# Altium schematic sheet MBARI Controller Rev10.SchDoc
size C
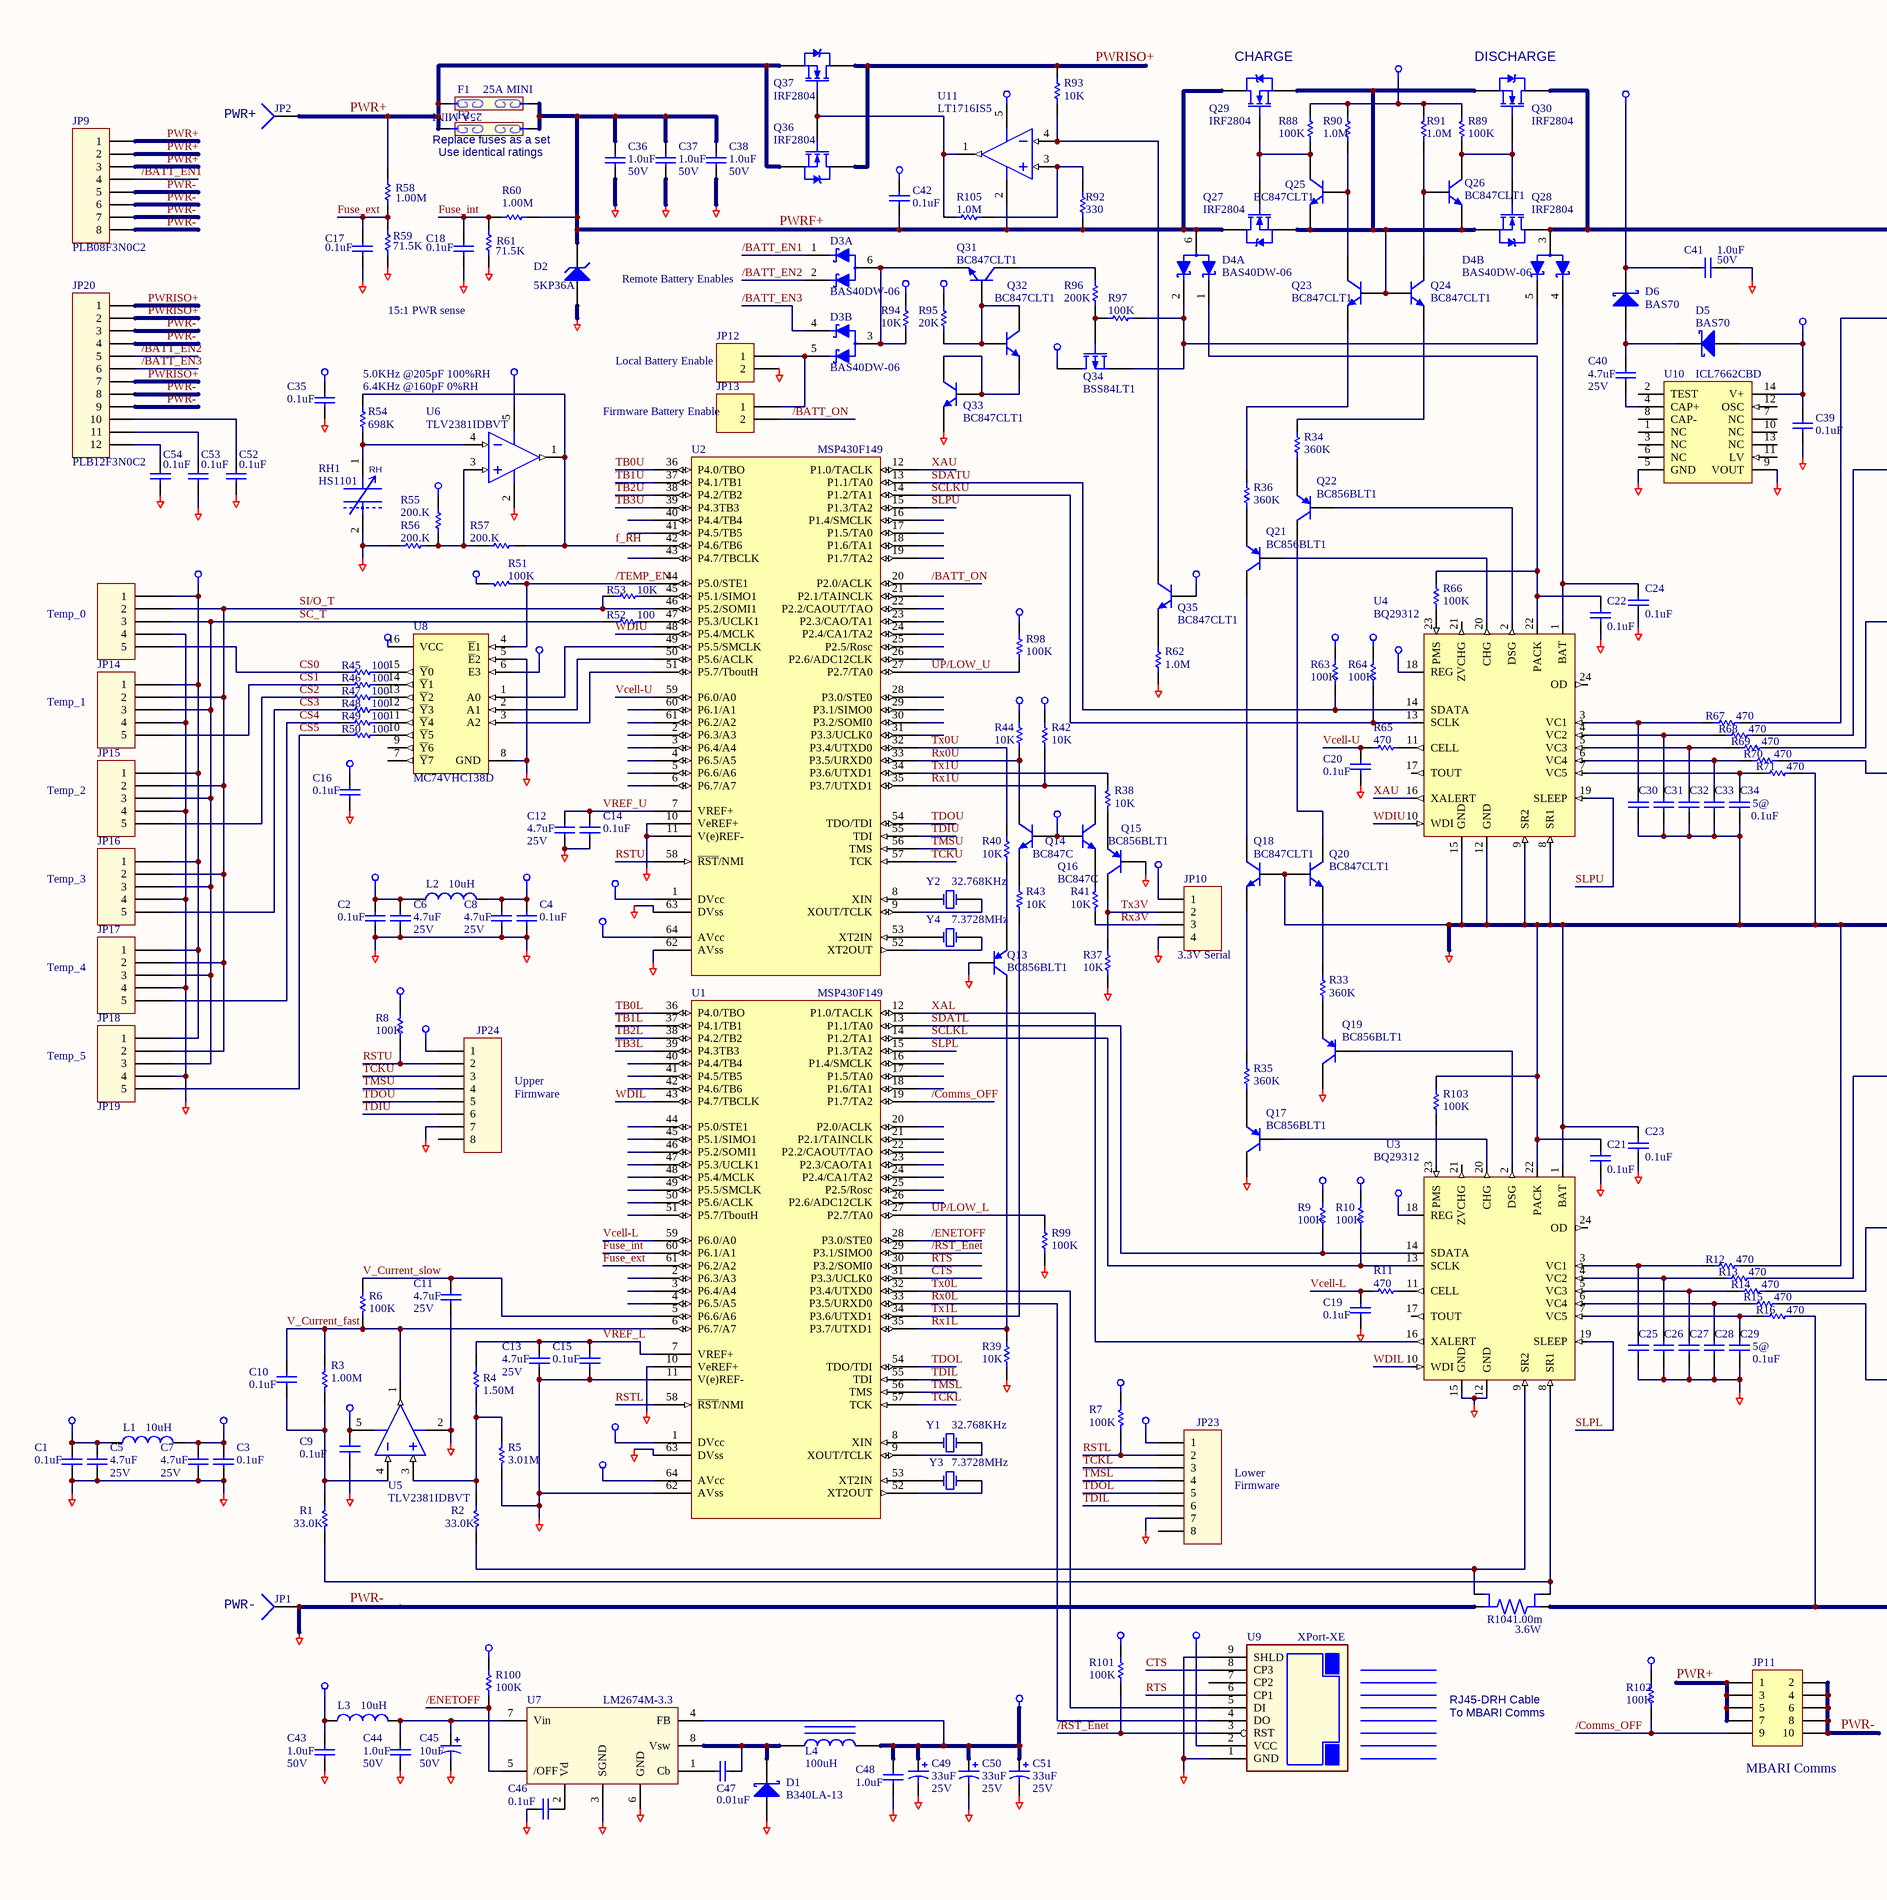
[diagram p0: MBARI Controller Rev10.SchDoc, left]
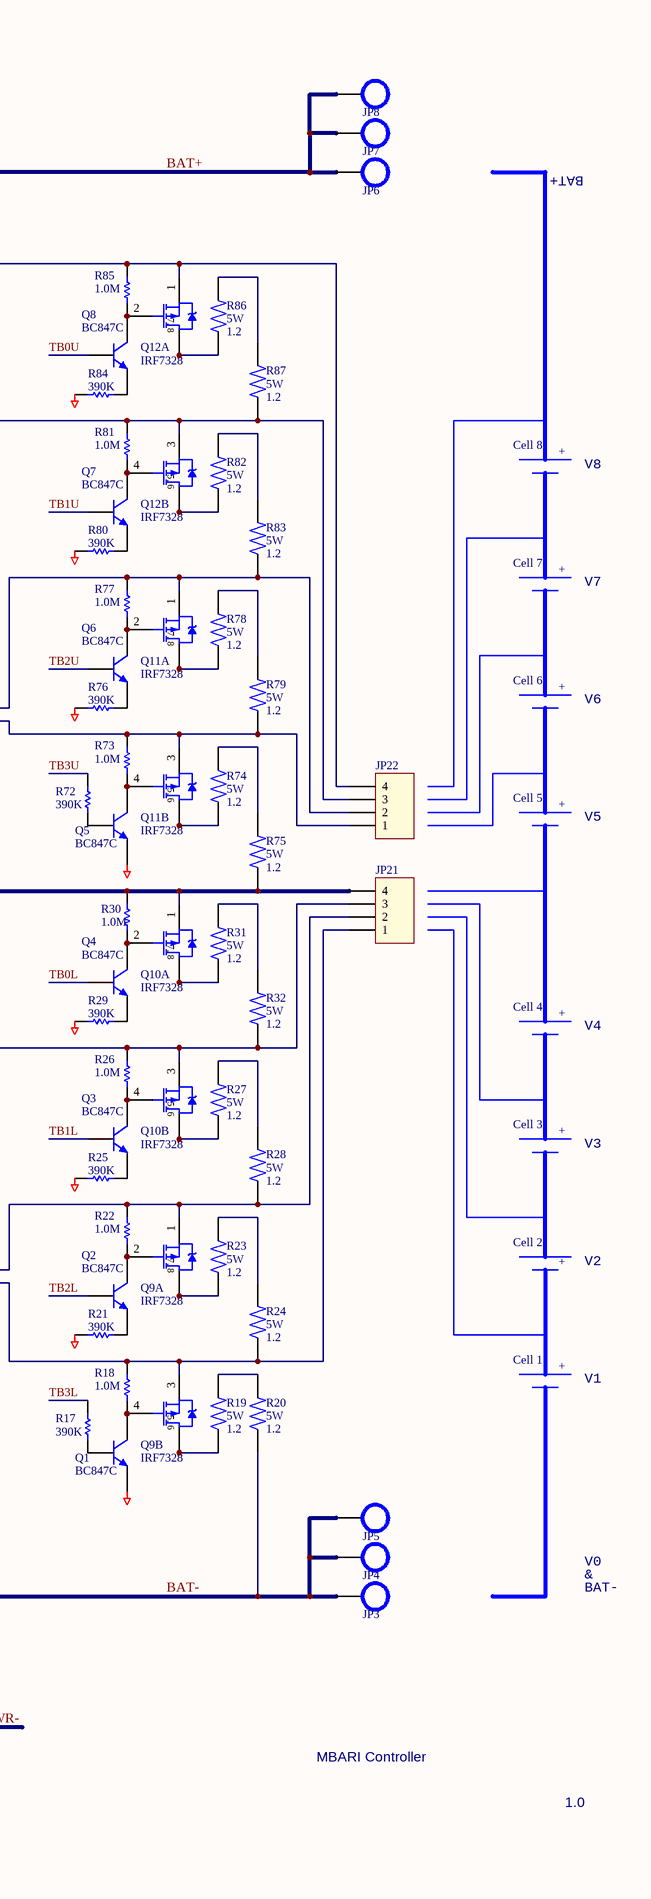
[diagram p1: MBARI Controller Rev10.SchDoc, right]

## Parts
C1  value 0.1uF  [0805]  (hidden comment: C0805)
C2  value 0.1uF  [0805]  (hidden comment: C0805)
C3  value 0.1uF  [0805]  (hidden comment: C0805)
C4  value 0.1uF  [0805]  (hidden comment: C0805)
C5  value 4.7uF  Voltage: 25V  [0805]  (hidden comment: C0805)
C6  value 4.7uF  Voltage: 25V  [0805]  (hidden comment: C0805)
C7  value 4.7uF  Voltage: 25V  [0805]  (hidden comment: C0805)
C8  value 4.7uF  Voltage: 25V  [0805]  (hidden comment: C0805)
C9  value 0.1uF  [0805]  (hidden comment: C0805)
C10  value 0.1uF  [0805]  (hidden comment: C0805)
C11  value 4.7uF  Voltage: 25V  [0805]  (hidden comment: C0805)
C12  value 4.7uF  Voltage: 25V  [0805]  (hidden comment: C0805)
C13  value 4.7uF  Voltage: 25V  [0805]  (hidden comment: C0805)
C14  value 0.1uF  [0805]  (hidden comment: C0805)
C15  value 0.1uF  [0805]  (hidden comment: C0805)
C16  value 0.1uF  [0805]  (hidden comment: C0805)
C17  value 0.1uF  [0805]  (hidden comment: C0805)
C18  value 0.1uF  [0805]  (hidden comment: C0805)
C19  value 0.1uF  [0805]  (hidden comment: C0805)
C20  value 0.1uF  [0805]  (hidden comment: C0805)
C21  value 0.1uF  [0805]  (hidden comment: C0805)
C22  value 0.1uF  [0805]  (hidden comment: C0805)
C23  value 0.1uF  [0805]  (hidden comment: C0805)
C24  value 0.1uF  [0805]  (hidden comment: C0805)
C25  C0805  [0805]  (value not drawn)
C26  C0805  [0805]  (value not drawn)
C27  C0805  [0805]  (value not drawn)
C28  C0805  [0805]  (value not drawn)
C29  value 0.1uF  [0805]  (hidden comment: C0805)
C30  C0805  [0805]  (value not drawn)
C31  C0805  [0805]  (value not drawn)
C32  C0805  [0805]  (value not drawn)
C33  C0805  [0805]  (value not drawn)
C34  value 0.1uF  [0805]  (hidden comment: C0805)
C35  value 0.1uF  [0805]  (hidden comment: C0805)
C36  value 1.0uF  Voltage: 50V  [0805]  (hidden comment: C0805)
C37  value 1.0uF  Voltage: 50V  [0805]  (hidden comment: C0805)
C38  value 1.0uF  Voltage: 50V  [0805]  (hidden comment: C0805)
C39  value 0.1uF  [0805]  (hidden comment: C0805)
C40  value 4.7uF  Voltage: 25V  [0805]  (hidden comment: C0805)
C41  value 1.0uF  Voltage: 50V  [0805]  (hidden comment: C0805)
C42  value 0.1uF  [0805]  (hidden comment: C0805)
C43  value 1.0uF  Voltage: 50V  [0805]  (hidden comment: C0805)
C44  value 1.0uF  Voltage: 50V  [0805]  (hidden comment: C0805)
C45  value 10uF  Voltage: 50V  [CAP S/M 6.3DIA]  (hidden comment: Cap Pol2)
C46  value 0.1uF  [0805]  (hidden comment: C0805)
C47  value 0.01uF  [0805]  (hidden comment: C0805)
C48  value 1.0uF  [0805]  (hidden comment: C0805)
C49  value 33uF  Voltage: 25V  [CAP S/M 6.3DIA]  (hidden comment: Cap Pol2)
C50  value 33uF  Voltage: 25V  [CAP S/M 6.3DIA]  (hidden comment: Cap Pol2)
C51  value 33uF  Voltage: 25V  [CAP S/M 6.3DIA]  (hidden comment: Cap Pol2)
C52  value 0.1uF  [0805]  (hidden comment: C0805)
C53  value 0.1uF  [0805]  (hidden comment: C0805)
C54  value 0.1uF  [0805]  (hidden comment: C0805)
D1  value B340LA-13  [SMA]  (hidden comment: IR 10MQ060N)
D2  value 5KP36A  [P600]  (hidden comment: D Zener)
D3  value BAS40DW-06  [SO-G6/Z2.8]  (parts A,B of 2)
D4  value BAS40DW-06  [SO-G6/Z2.8]  (parts A,B of 2)
D5  value BAS70  [SO-G3/C2.5]  (hidden comment: Diode BAS70)
D6  value BAS70  [SO-G3/C2.5]  (hidden comment: Diode BAS70)
F1  (no value)  [Fuseclip Mini pcb]
F2  (no value)  [Fuseclip Mini pcb]
JP1  Socket  [Terminal - screw]  (value not drawn)
JP2  Socket  [Terminal - screw]  (value not drawn)
JP3  TERMINAL 10AWG  [Terminal 10AWG crimp]  (value not drawn)
JP4  TERMINAL 10AWG  [Terminal 10AWG crimp]  (value not drawn)
JP5  TERMINAL 10AWG  [Terminal 10AWG crimp]  (value not drawn)
JP6  TERMINAL 10AWG  [Terminal 10AWG crimp]  (value not drawn)
JP7  TERMINAL 10AWG  [Terminal 10AWG crimp]  (value not drawn)
JP8  TERMINAL 10AWG  [Terminal 10AWG crimp]  (value not drawn)
JP9  value PLB08F3N0C2  [PLB08F3]  (hidden comment: Female)
JP10  HEADER 4 SHROUDED  [MTA-100-4 Shrouded]  (value not drawn)
JP11  Header 5X2  [MBARI IO -ept]  (value not drawn)
JP12  Header 2  [HDR1X2]  (value not drawn)
JP13  Header 2  [HDR1X2]  (value not drawn)
JP14  (no value)  [Header 5 MTA50]
JP15  (no value)  [Header 5 MTA50]
JP16  (no value)  [Header 5 MTA50]
JP17  (no value)  [Header 5 MTA50]
JP18  (no value)  [Header 5 MTA50]
JP19  (no value)  [Header 5 MTA50]
JP20  value PLB12F3N0C2  [PLB12F3]  (hidden comment: Female)
JP21  HEADER 4 SHROUDED  [MTA-100-4 Shrouded]  (value not drawn)
JP22  HEADER 4 SHROUDED  [MTA-100-4 Shrouded]  (value not drawn)
JP23  HEADER 8F LOW  [Header 4x2 2mm fem low]  (value not drawn)
JP24  HEADER 8F LOW  [Header 4x2 2mm fem low]  (value not drawn)
L1  value 10uH  [CC2012-0805]  (hidden comment: LQM21FN100N00L)
L2  value 10uH  [CC2012-0805]  (hidden comment: LQM21FN100N00L)
L3  value 10uH  [CC2012-0805]  (hidden comment: LQM21FN100N00L)
L4  value 100uH  [CDR125]  (hidden comment: Inductor Iron)
Q1  BC847C  [SOT23]
Q2  BC847C  [SOT23]
Q3  BC847C  [SOT23]
Q4  BC847C  [SOT23]
Q5  BC847C  [SOT23]
Q6  BC847C  [SOT23]
Q7  BC847C  [SOT23]
Q8  BC847C  [SOT23]
Q9  IRF7328  [SO-8]  (parts A,B of 2)
Q10  IRF7328  [SO-8]  (parts A,B of 2)
Q11  IRF7328  [SO-8]  (parts A,B of 2)
Q12  IRF7328  [SO-8]  (parts A,B of 2)
Q13  BC856BLT1  [318-08]
Q14  BC847C  [SOT23]
Q15  BC856BLT1  [318-08]
Q16  BC847C  [SOT23]
Q17  BC856BLT1  [318-08]
Q18  BC847CLT1  [318-08]
Q19  BC856BLT1  [318-08]
Q20  BC847CLT1  [318-08]
Q21  BC856BLT1  [318-08]
Q22  BC856BLT1  [318-08]
Q23  BC847CLT1  [318-08]
Q24  BC847CLT1  [318-08]
Q25  BC847CLT1  [318-08]
Q26  BC847CLT1  [318-08]
Q27  IRF2804  [TO-220AB]
Q28  IRF2804  [TO-220AB]
Q29  IRF2804  [TO-220AB]
Q30  IRF2804  [TO-220AB]
Q31  BC847CLT1  [318-08]
Q32  BC847CLT1  [318-08]
Q33  BC847CLT1  [318-08]
Q34  BSS84LT1  [SOT23]
Q35  BC847CLT1  [318-08]
Q36  IRF2804  [TO-220AB]
Q37  IRF2804  [TO-220AB]
R1  value 33.0K  [C0805]  (hidden comment: ERJ6GE)
R2  value 33.0K  [C0805]  (hidden comment: ERJ6GE)
R3  value 1.00M  [C0805]  (hidden comment: ERJ6GE)
R4  value 1.50M  [C0805]  (hidden comment: ERJ6GE)
R5  value 3.01M  [C0805]  (hidden comment: ERJ6GE)
R6  value 100K  [C0805]  (hidden comment: ERJ6GE)
R7  value 100K  [C0805]  (hidden comment: ERJ6GE)
R8  value 100K  [C0805]  (hidden comment: ERJ6GE)
R9  value 100K  [C0805]  (hidden comment: ERJ6GE)
R10  value 100K  [C0805]  (hidden comment: ERJ6GE)
R11  value 470  [C0805]  (hidden comment: ERJ6GE)
R12  value 470  [C0805]  (hidden comment: ERJ6GE)
R13  value 470  [C0805]  (hidden comment: ERJ6GE)
R14  value 470  [C0805]  (hidden comment: ERJ6GE)
R15  value 470  [C0805]  (hidden comment: ERJ6GE)
R16  value 470  [C0805]  (hidden comment: ERJ6GE)
R17  value 390K  [C0805]  (hidden comment: ERJ6GE)
R18  value 1.0M  [C0805]  (hidden comment: ERJ6GE)
R19  value 1.2  Power: 5W  [Resistor 5W - ceramic]
R20  value 1.2  Power: 5W  [Resistor 5W - ceramic]
R21  value 390K  [C0805]  (hidden comment: ERJ6GE)
R22  value 1.0M  [C0805]  (hidden comment: ERJ6GE)
R23  value 1.2  Power: 5W  [Resistor 5W - ceramic]
R24  value 1.2  Power: 5W  [Resistor 5W - ceramic]
R25  value 390K  [C0805]  (hidden comment: ERJ6GE)
R26  value 1.0M  [C0805]  (hidden comment: ERJ6GE)
R27  value 1.2  Power: 5W  [Resistor 5W - ceramic]
R28  value 1.2  Power: 5W  [Resistor 5W - ceramic]
R29  value 390K  [C0805]  (hidden comment: ERJ6GE)
R30  value 1.0M  [C0805]  (hidden comment: ERJ6GE)
R31  value 1.2  Power: 5W  [Resistor 5W - ceramic]
R32  value 1.2  Power: 5W  [Resistor 5W - ceramic]
R33  value 360K  [C0805]  (hidden comment: ERJ6GE)
R34  value 360K  [C0805]  (hidden comment: ERJ6GE)
R35  value 360K  [C0805]  (hidden comment: ERJ6GE)
R36  value 360K  [C0805]  (hidden comment: ERJ6GE)
R37  value 10K  [C0805]  (hidden comment: ERJ6GE)
R38  value 10K  [C0805]  (hidden comment: ERJ6GE)
R39  value 10K  [C0805]  (hidden comment: ERJ6GE)
R40  value 10K  [C0805]  (hidden comment: ERJ6GE)
R41  value 10K  [C0805]  (hidden comment: ERJ6GE)
R42  value 10K  [C0805]  (hidden comment: ERJ6GE)
R43  value 10K  [C0805]  (hidden comment: ERJ6GE)
R44  value 10K  [C0805]  (hidden comment: ERJ6GE)
R45  value 100  [C0805]  (hidden comment: ERJ6GE)
R46  value 100  [C0805]  (hidden comment: ERJ6GE)
R47  value 100  [C0805]  (hidden comment: ERJ6GE)
R48  value 100  [C0805]  (hidden comment: ERJ6GE)
R49  value 100  [C0805]  (hidden comment: ERJ6GE)
R50  value 100  [C0805]  (hidden comment: ERJ6GE)
R51  value 100K  [C0805]  (hidden comment: ERJ6GE)
R52  value 100  [C0805]  (hidden comment: ERJ6GE)
R53  value 10K  [C0805]  (hidden comment: ERJ6GE)
R54  value 698K  [C0805]  (hidden comment: ERJ6GE)
R55  value 200.K  [C0805]  (hidden comment: ERJ6GE)
R56  value 200.K  [C0805]  (hidden comment: ERJ6GE)
R57  value 200.K  [C0805]  (hidden comment: ERJ6GE)
R58  value 1.00M  [C0805]  (hidden comment: ERJ6GE)
R59  value 71.5K  [C0805]  (hidden comment: ERJ6GE)
R60  value 1.00M  [C0805]  (hidden comment: ERJ6GE)
R61  value 71.5K  [C0805]  (hidden comment: ERJ6GE)
R62  value 1.0M  [C0805]  (hidden comment: ERJ6GE)
R63  value 100K  [C0805]  (hidden comment: ERJ6GE)
R64  value 100K  [C0805]  (hidden comment: ERJ6GE)
R65  value 470  [C0805]  (hidden comment: ERJ6GE)
R66  value 100K  [C0805]  (hidden comment: ERJ6GE)
R67  value 470  [C0805]  (hidden comment: ERJ6GE)
R68  value 470  [C0805]  (hidden comment: ERJ6GE)
R69  value 470  [C0805]  (hidden comment: ERJ6GE)
R70  value 470  [C0805]  (hidden comment: ERJ6GE)
R71  value 470  [C0805]  (hidden comment: ERJ6GE)
R72  value 390K  [C0805]  (hidden comment: ERJ6GE)
R73  value 1.0M  [C0805]  (hidden comment: ERJ6GE)
R74  value 1.2  Power: 5W  [Resistor 5W - ceramic]
R75  value 1.2  Power: 5W  [Resistor 5W - ceramic]
R76  value 390K  [C0805]  (hidden comment: ERJ6GE)
R77  value 1.0M  [C0805]  (hidden comment: ERJ6GE)
R78  value 1.2  Power: 5W  [Resistor 5W - ceramic]
R79  value 1.2  Power: 5W  [Resistor 5W - ceramic]
R80  value 390K  [C0805]  (hidden comment: ERJ6GE)
R81  value 1.0M  [C0805]  (hidden comment: ERJ6GE)
R82  value 1.2  Power: 5W  [Resistor 5W - ceramic]
R83  value 1.2  Power: 5W  [Resistor 5W - ceramic]
R84  value 390K  [C0805]  (hidden comment: ERJ6GE)
R85  value 1.0M  [C0805]  (hidden comment: ERJ6GE)
R86  value 1.2  Power: 5W  [Resistor 5W - ceramic]
R87  value 1.2  Power: 5W  [Resistor 5W - ceramic]
R88  value 100K  [C0805]  (hidden comment: ERJ6GE)
R89  value 100K  [C0805]  (hidden comment: ERJ6GE)
R90  value 1.0M  [C0805]  (hidden comment: ERJ6GE)
R91  value 1.0M  [C0805]  (hidden comment: ERJ6GE)
R92  value 330  [C0805]  (hidden comment: ERJ6GE)
R93  value 10K  [C0805]  (hidden comment: ERJ6GE)
R94  value 10K  [C0805]  (hidden comment: ERJ6GE)
R95  value 20K  [C0805]  (hidden comment: ERJ6GE)
R96  value 200K  [C0805]  (hidden comment: ERJ6GE)
R97  value 100K  [C0805]  (hidden comment: ERJ6GE)
R98  value 100K  [C0805]  (hidden comment: ERJ6GE)
R99  value 100K  [C0805]  (hidden comment: ERJ6GE)
R100  value 100K  [C0805]  (hidden comment: ERJ6GE)
R101  value 100K  [C0805]  (hidden comment: ERJ6GE)
R102  value 100K  [C0805]  (hidden comment: ERJ6GE)
R103  value 100K  [C0805]  (hidden comment: ERJ6GE)
R104  value 1.00m  Power: 3.6W  [Shunt PCB-BH-50-50]  (hidden comment: Resistor Shunt 4-term)
R105  value 1.0M  [C0805]  (hidden comment: ERJ6GE)
RH1  HS1101  [HS1101]
U1  value MSP430F149  [F-QFP10x10-G64/N]
U2  value MSP430F149  [F-QFP10X10-G64/N]
U3  BQ29312  [SSO-G24/P.65]
U4  BQ29312  [SSO-G24/P.65]
U5  value TLV2381IDBVT  [MA05A]  (hidden comment: LM7131ACM5)
U6  value TLV2381IDBVT  [MA05A]  (hidden comment: LM7131ACM5)
U7  value LM2674M-3.3  [SO-G8]  (hidden comment: Max5033)
U8  MC74VHC138D  [751B-05]
U9  value XPort-XE  [XPort]  (hidden comment: XPort)
U10  ICL7662CBD  [NSO14]
U11  value LT1716IS5  [SOT23-5]  (hidden comment: MAX9075EUK-T)
Y1  value 32.768KHz  [Cylinder 3.2mm]  (hidden comment: 32kHz)
Y2  value 32.768KHz  [Cylinder 3.2mm]  (hidden comment: 32kHz)
Y3  7.3728MHz  [Cylinder 3.2mm]
Y4  7.3728MHz  [Cylinder 3.2mm]

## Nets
+3DL: C1.2 C5.1 JP10.1 JP23.1 L1.1 Q14.1(B) Q16.1(B) R7.1 R100.2 R102.1 U1.1(DVcc)
+3DU: C2.2 C6.1 C16.2 C35.2 JP14.1 JP15.1 JP16.1 JP17.1 JP18.1 JP19.1 JP24.1 L2.1 R8.1 R42.2 R44.2 R51.1 R55.2 R98.1 U2.1(DVcc) U6.5(V+) U8.6(E3) U8.16(VCC)
+3H: C48.2 C49.1 C50.1 C51.1 L4.2 R101.2 U7.4(FB) U9.2(VCC)
+3L: C3.2 C7.1 C9.2 L1.2 R9.1 R10.1 R94.2 R95.2 U1.64(AVcc) U3.18(REG) U5.5(V+)
+3U: C4.2 C8.1 L2.2 Q35.1(B) R63.1 R64.1 U2.64(AVcc) U4.18(REG)
AGNDU: C2.1 C4.1 C6.2 C8.2 C12.2 C14.1 C16.1 C20.1 C21.2 C22.1 C23.2 C24.1 C30.1 C31.1 C32.1 C33.1 C34.1 C35.1 C39.1 C41.2 JP14.4 JP15.4 JP16.4 JP17.4 JP18.4 JP19.4 JP21.4 JP24.7 Q5.2(E) Q10.1(S) Q13.1(B) Q15.1(B) Q18.1(B) Q20.1(B) R12.1 R30.2 R56.1 R62.2 R71.1 R75.2 R76.1 R80.1 R84.1 R103.2 RH1.2(Case) U2.10(VeREF+) U2.11(V(e)REF-) U2.62(AVss) U2.63(DVss) U3.1(BAT) U3.22(PACK) U4.8(SR1) U4.9(SR2) U4.12(GND) U4.15(GND) U6.2(V-) U8.5(~{E}2) U8.8(GND) U10.5(GND) U10.9(VOUT)  [also labelled DGNDU]
PWR-: C1.1 C3.1 C5.2 C7.2 C9.1 C11.2 C13.2 C15.1 C17.1 C18.1 C19.1 C21.1 C23.1 C25.1 C26.1 C27.1 C28.1 C29.1 C36.1 C37.1 C38.1 C43.1 C44.1 C45.2 C46.2 C48.1 C49.2 C50.2 C51.2 C52.1 C53.1 C54.1 D1.1(A) D2.1(A) JP1.1 JP9.5 JP9.6 JP9.7 JP9.8 JP10.4 JP11.2 JP11.4 JP11.6 JP11.8 JP11.10 JP12.2 JP20.3 JP20.4 JP20.8 JP20.9 JP23.7 Q1.2(E) Q17.3(C) Q19.3(C) Q33.2(E) R5.2 R21.1 R25.1 R29.1 R37.1 R39.1 R59.1 R61.1 R99.1 R104.1 U1.10(VeREF+) U1.11(V(e)REF-) U1.62(AVss) U1.63(DVss) U3.12(GND) U3.15(GND) U5.2(V-) U7.3(SGND) U7.6(GND) U9.1(GND) U9.9(SHLD)  [also labelled AGNDL, DGNDL]
V_Gate: C41.1 C42.2 D6.3(K) R88.2 R89.2 R90.2 R91.2 U11.5(V+)
V_on: C39.2 C43.2 D5.1(A) L3.1 Q34.1(D) U10.14(V+)
/BATT_EN1: D3.1(K1) JP9.4
/BATT_EN2: D3.2(K2) JP20.5
/BATT_EN3: D3.4(K3) JP20.6
/BATT_ON: JP13.2 U2.20(P2.0/ACLK)
/Comms_OFF: JP11.9 R102.2 U1.19(P1.7/TA2)
/ENETOFF: R100.1 U1.28(P3.0/STE0) U7.5(/OFF)
/RST_Enet: R101.1 U1.29(P3.1/SIMO0) U9.3(RST)
/TEMP_EN: R51.2 U2.44(P5.0/STE1) U8.4(~{E}1)
BAT+: D4.3(A34) JP6.1 JP7.1 JP8.1 Q28.2(D) Q30.2(D)
BAT-: JP3.1 JP4.1 JP5.1 R16.1 R20.2 R104.4
CS0: JP14.5 R45.2
CS1: JP15.5 R46.2
CS2: JP16.5 R47.2
CS3: JP17.5 R48.2
CS4: JP18.5 R49.2
CS5: JP19.5 R50.2
CTS: U1.31(P3.3/UCLK0) U9.8(CP3)
f_RH: R54.2 R57.2 U2.42(P4.6/TB6) U6.1(OUT)
Fuse_ext: C17.2 R58.1 R59.2 U1.61(P6.2/A2)
Fuse_int: C18.2 R60.1 R61.2 U1.60(P6.1/A1)
PWR+: F1.1 F2.1 JP2.1 JP9.1 JP9.2 JP9.3 JP11.1 JP11.3 JP11.5 JP11.7 Q36.3(S) Q37.3(S) R58.2
PWRF+: C36.2 C37.2 C38.2 C42.1 D2.2(K) D4.6(A12) F1.2 F2.2 Q27.2(D) Q29.2(D) R60.2 R92.1 U11.2(GND)
PWRISO+: JP20.1 JP20.2 JP20.7 Q36.2(D) Q37.2(D) R93.1
RSTL: JP23.2 R7.2 U1.58(~{RST}/NMI)
RSTU: JP24.2 R8.2 U2.58(~{RST}/NMI)
RTS: U1.30(P3.2/SOMI0) U9.6(CP1)
Rx0L: U1.33(P3.5/URXD0) U9.4(DO)
Rx0U: Q14.3(C) R44.1 U2.33(P3.5/URXD0)
Rx1L: Q13.3(C) R39.2 U1.35(P3.7/UTXD1)
Rx1U: Q16.3(C) R42.1 U2.35(P3.7/UTXD1)
Rx3V: JP10.3 R41.2
SC_T: JP14.3 JP15.3 JP16.3 JP17.3 JP18.3 JP19.3 R52.2
SCLKL: R10.2 U1.14(P1.2/TA1) U3.13(SCLK)
SCLKU: R64.2 U2.14(P1.2/TA1) U4.13(SCLK)
SDATL: R9.2 U1.13(P1.1/TA0) U3.14(SDATA)
SDATU: R63.2 U2.13(P1.1/TA0) U4.14(SDATA)
SI/O_T: JP14.2 JP15.2 JP16.2 JP17.2 JP18.2 JP19.2 R53.2 U2.46(P5.2/SOMI1)
SLPL: U1.15(P1.3/TA2) U3.19(SLEEP)
SLPU: U2.15(P1.3/TA2) U4.19(SLEEP)
TB0L: Q4.1(B) U1.36(P4.0/TBO)
TB0U: Q8.1(B) U2.36(P4.0/TBO)
TB1L: Q3.1(B) U1.37(P4.1/TB1)
TB1U: Q7.1(B) U2.37(P4.1/TB1)
TB2L: Q2.1(B) U1.38(P4.2/TB2)
TB2U: Q6.1(B) U2.38(P4.2/TB2)
TB3L: R17.1 U1.39(P4.3TB3)
TB3U: R72.1 U2.39(P4.3TB3)
TCKL: JP23.3 U1.57(TCK)
TCKU: JP24.3 U2.57(TCK)
TDIL: JP23.6 U1.55(TDI)
TDIU: JP24.6 U2.55(TDI)
TDOL: JP23.5 U1.54(TDO/TDI)
TDOU: JP24.5 U2.54(TDO/TDI)
TMSL: JP23.4 U1.56(TMS)
TMSU: JP24.4 U2.56(TMS)
Tx0L: U1.32(P3.4/UTXD0) U9.5(DI)
Tx0U: R40.2 U2.32(P3.4/UTXD0)
Tx1L: R43.2 U1.34(P3.6/UTXD1)
Tx1U: R38.2 U2.34(P3.6/UTXD1)
Tx3V: JP10.2 Q15.3(C) R37.2
UP/LOW_L: R99.2 U1.27(P2.7/TA0)
UP/LOW_U: R98.2 U2.27(P2.7/TA0)
V_Current_fast: C10.2 R3.1 R6.2 U1.6(P6.7/A7) U5.1(OUT)
V_Current_slow: C11.1 R6.1 U1.5(P6.6/A6)
Vcell-L: C19.2 R11.2 U1.59(P6.0/A0)
Vcell-U: C20.2 R65.2 U2.59(P6.0/A0)
VREF_L: C13.1 C15.2 R4.1 U1.7(VREF+)
VREF_U: C12.1 C14.2 U2.7(VREF+)
WDIL: U1.43(P4.7/TBCLK) U3.10(WDI)
WDIU: U2.48(P5.4/MCLK) U4.10(WDI)
XAL: U1.12(P1.0/TACLK) U3.16(XALERT)
XAU: U2.12(P1.0/TACLK) U4.16(XALERT)
NetC10_1: C10.1 R1.1 R3.2 U5.4(IN-)
NetC22_2: C22.2 D4.1(K1) R66.2 U4.22(PACK)
NetC24_2: C24.2 D4.4(K3) U4.1(BAT)
NetC25_2: C25.2 R12.2 U3.3(VC1)
NetC26_2: C26.2 R13.2 U3.4(VC2)
NetC27_2: C27.2 R14.2 U3.5(VC3)
NetC28_2: C28.2 R15.2 U3.6(VC4)
NetC29_2: C29.2 R16.2 U3.7(VC5)
NetC30_2: C30.2 R67.2 U4.3(VC1)
NetC31_2: C31.2 R68.2 U4.4(VC2)
NetC32_2: C32.2 R69.2 U4.5(VC3)
NetC33_2: C33.2 R70.2 U4.6(VC4)
NetC34_2: C34.2 R71.2 U4.7(VC5)
NetC40_1: C40.1 D5.3(K) D6.1(A)
NetC40_2: C40.2 U10.4(CAP+)
NetC44_2: C44.2 C45.1 L3.2 U7.7(Vin)
NetC46_1: C46.1 U7.2(Vd)
NetC47_1: C47.1 U7.1(Cb)
NetC47_2: C47.2 D1.2(K) L4.1 U7.8(Vsw)
NetC52_2: C52.2 JP20.10
NetC53_2: C53.2 JP20.11
NetC54_2: C54.2 JP20.12
NetD3_3: D3.3(A34) D3.6(A12) Q31.2(E) R94.1
NetD3_5: D3.5(K4) JP12.1 JP13.1
NetD4_2: D4.2(K2) D4.5(K4) Q34.2(S) R97.2
NetJP21_1: JP21.1 Q9.3(S) R15.1 R18.2 R24.2
NetJP21_2: JP21.2 Q9.1(S) R14.1 R22.2 R28.2
NetJP21_3: JP21.3 Q10.3(S) R13.1 R26.2 R32.2
NetJP22_1: JP22.1 Q11.3(S) R70.1 R73.2 R79.2
NetJP22_2: JP22.2 Q11.1(S) R69.1 R77.2 R83.2
NetJP22_3: JP22.3 Q12.3(S) R68.1 R81.2 R87.2
NetJP22_4: JP22.4 Q12.1(S) R67.1 R85.2
NetQ1_1: Q1.1(B) R17.2
NetQ1_3: Q1.3(C) Q9.4(G) R18.1
NetQ2_2: Q2.2(E) R21.2
NetQ2_3: Q2.3(C) Q9.2(G) R22.1
NetQ3_2: Q3.2(E) R25.2
NetQ3_3: Q3.3(C) Q10.4(G) R26.1
NetQ4_2: Q4.2(E) R29.2
NetQ4_3: Q4.3(C) Q10.2(G) R30.1
NetQ5_1: Q5.1(B) R72.2
NetQ5_3: Q5.3(C) Q11.4(G) R73.1
NetQ6_2: Q6.2(E) R76.2
NetQ6_3: Q6.3(C) Q11.2(G) R77.1
NetQ7_2: Q7.2(E) R80.2
NetQ7_3: Q7.3(C) Q12.4(G) R81.1
NetQ8_2: Q8.2(E) R84.2
NetQ8_3: Q8.3(C) Q12.2(G) R85.1
NetQ9_5: Q9.5(D) Q9.6(D) R19.1
NetQ9_7: Q9.7(D) Q9.8(D) R23.1
NetQ10_5: Q10.5(D) Q10.6(D) R27.1
NetQ10_7: Q10.7(D) Q10.8(D) R31.1
NetQ11_5: Q11.5(D) Q11.6(D) R74.1
NetQ11_7: Q11.7(D) Q11.8(D) R78.1
NetQ12_5: Q12.5(D) Q12.6(D) R82.1
NetQ12_7: Q12.7(D) Q12.8(D) R86.1
NetQ13_2: Q13.2(E) R40.1
NetQ14_2: Q14.2(E) R43.1
NetQ15_2: Q15.2(E) R38.1
NetQ16_2: Q16.2(E) R41.1
NetQ17_1: Q17.1(B) U3.20(CHG)
NetQ17_2: Q17.2(E) R35.1
NetQ18_2: Q18.2(E) R35.2
NetQ18_3: Q18.3(C) Q21.3(C)
NetQ19_1: Q19.1(B) U3.2(DSG)
NetQ19_2: Q19.2(E) R33.1
NetQ20_2: Q20.2(E) R33.2
NetQ20_3: Q20.3(C) Q22.3(C)
NetQ21_1: Q21.1(B) U4.20(CHG)
NetQ21_2: Q21.2(E) R36.1
NetQ22_1: Q22.1(B) U4.2(DSG)
NetQ22_2: Q22.2(E) R34.1
NetQ23_1: Q23.1(B) Q24.1(B) Q25.2(E) Q26.2(E) Q27.3(S) Q28.3(S) Q29.3(S) Q30.3(S)
NetQ23_2: Q23.2(E) R36.2
NetQ23_3: Q23.3(C) Q25.1(B) R90.1
NetQ24_2: Q24.2(E) R34.2
NetQ24_3: Q24.3(C) Q26.1(B) R91.1
NetQ25_3: Q25.3(C) Q27.1(G) Q29.1(G) R88.1
NetQ26_3: Q26.3(C) Q28.1(G) Q30.1(G) R89.1
NetQ31_1: Q31.1(B) Q32.1(B) Q32.3(C) R95.1
NetQ31_3: Q31.3(C) R96.1
NetQ32_2: Q32.2(E) Q33.1(B) Q33.3(C)
NetQ34_3: Q34.3(G) R96.2 R97.1
NetQ35_2: Q35.2(E) R62.1
NetQ35_3: Q35.3(C) R93.2 U11.4(IN-)
NetQ36_1: Q36.1(G) Q37.1(G) R105.2 U11.1(OUT)
NetR1_2: R1.2 R104.3 U3.8(SR1)
NetR2_1: R2.1 R4.2 R5.1 U5.3(IN+)
NetR2_2: R2.2 R104.2 U3.9(SR2)
NetR11_1: R11.1 U3.11(CELL)
NetR19_2: R19.2 R20.1
NetR23_2: R23.2 R24.1
NetR27_2: R27.2 R28.1
NetR31_2: R31.2 R32.1
NetR45_1: R45.1 U8.15(~{Y}0)
NetR46_1: R46.1 U8.14(~{Y}1)
NetR47_1: R47.1 U8.13(~{Y}2)
NetR48_1: R48.1 U8.12(~{Y}3)
NetR49_1: R49.1 U8.11(~{Y}4)
NetR50_1: R50.1 U8.10(~{Y}5)
NetR52_1: R52.1 U2.47(P5.3/UCLK1)
NetR53_1: R53.1 U2.45(P5.1/SIMO1)
NetR54_1: R54.1 RH1.1(Active) U6.4(IN-)
NetR55_1: R55.1 R56.2 R57.1 U6.3(IN+)
NetR65_1: R65.1 U4.11(CELL)
NetR66_1: R66.1 U4.23(PMS)
NetR74_2: R74.2 R75.1
NetR78_2: R78.2 R79.1
NetR82_2: R82.2 R83.1
NetR86_2: R86.2 R87.1
NetR92_2: R92.2 R105.1 U11.3(IN+)
NetR103_1: R103.1 U3.23(PMS)
NetU1_8: U1.8(XIN) Y1.2(OSC2)
NetU1_9: U1.9(XOUT/TCLK) Y1.1(OSC1)
NetU1_52: U1.52(XT2OUT) Y3.1(OSC1)
NetU1_53: U1.53(XT2IN) Y3.2(OSC2)
NetU2_8: U2.8(XIN) Y2.2(OSC2)
NetU2_9: U2.9(XOUT/TCLK) Y2.1(OSC1)
NetU2_49: U2.49(P5.5/SMCLK) U8.1(A0)
NetU2_50: U2.50(P5.6/ACLK) U8.2(A1)
NetU2_51: U2.51(P5.7/TboutH) U8.3(A2)
NetU2_52: U2.52(XT2OUT) Y4.1(OSC1)
NetU2_53: U2.53(XT2IN) Y4.2(OSC2)

Not connected (* = marked no-connect by the designer): JP23 8; JP24 8; U1 2(P6.3/A3) 3(P6.4/A4) 4(P6.5/A5) 16(P1.4/SMCLK) 17(P1.5/TA0) 18(P1.6/TA1) 20(P2.0/ACLK) 21(P2.1/TAINCLK) 22(P2.2/CAOUT/TAO) 23(P2.3/CAO/TA1) 24(P2.4/CA1/TA2) 25(P2.5/Rosc) 26(P2.6/ADC12CLK) 40(P4.4/TB4) 41(P4.5/TB5) 42(P4.6/TB6) 44(P5.0/STE1) 45(P5.1/SIMO1) 46(P5.2/SOMI1) 47(P5.3/UCLK1) 48(P5.4/MCLK) 49(P5.5/SMCLK) 50(P5.6/ACLK) 51(P5.7/TboutH); U2 2(P6.3/A3) 3(P6.4/A4) 4(P6.5/A5) 5(P6.6/A6) 6(P6.7/A7) 16(P1.4/SMCLK) 17(P1.5/TA0) 18(P1.6/TA1) 19(P1.7/TA2) 21(P2.1/TAINCLK) 22(P2.2/CAOUT/TAO) 23(P2.3/CAO/TA1) 24(P2.4/CA1/TA2) 25(P2.5/Rosc) 26(P2.6/ADC12CLK) 28(P3.0/STE0) 29(P3.1/SIMO0) 30(P3.2/SOMI0) 31(P3.3/UCLK0) 40(P4.4/TB4) 41(P4.5/TB5) 43(P4.7/TBCLK) 60(P6.1/A1) 61(P6.2/A2); U3 17(TOUT) 21(ZVCHG) 24(OD); U4 17(TOUT) 21(ZVCHG) 24(OD); U8 7(~{Y}7) 9(~{Y}6); U9 7(CP2); U10 1(NC) 2(TEST) 3(NC) 6(NC) 7(NC) 8(CAP-) 10(NC) 11(LV) 12(OSC) 13(NC)

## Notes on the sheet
- (near Q29) CHARGE
- (near Q30) DISCHARGE
- (near JP2) PWR+
- (near F2) Replace fuses as a set
- (near F1) 25A MINI
- 25A MINI
- (near F2) Use identical ratings
- BAT+
- 15:1 PWR sense
- Remote Battery Enables
- 5.0KHz @205pF 100%RH
- (near R54) 6.4KHz @160pF 0%RH
- (near JP12) Local Battery Enable
- (near JP13) Firmware Battery Enable
- Cell 8
- +
- V8
- Temp_0
- Cell 7
- V7
- Temp_1
- Cell 6
- V6
- Temp_2
- (near C34) 5@
- Temp_3
- Cell 5
- V5
- (near JP10) 3.3V Serial
- Temp_4
- Temp_5
- Upper
- Cell 4
- V4
- Firmware
- Cell 3
- V3
- Cell 2
- V2
- (near C29) 5@
- Cell 1
- V1
- Lower
- V0
- &
- (near JP1) PWR-
- BAT-
- RJ45-DRH Cable
- To MBARI Comms
- (near JP11) MBARI Comms
- MBARI Controller
- 1.0

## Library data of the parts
C1-C4 C9 C10 C14-C24 C29 C34 C35 C39 C42 C46 C47 C52-C54 = C0805: Ceramic Chip Capacitor - Standard; Revision 1: 11-Dec-2002: PCB footprint altered.; Revision 2: 19-Mar-2004: Silkscreen size reduced.; Package Information: Latest Revision: Mar-2001; Note: Footprint corresponds to dimensions for bulk cassette packaging. This case size has tightened tolerances.; Code - IPC: 2012[0805]
C5-C8 C11-C13 C40 = C0805: Ceramic Chip Capacitor - Standard; Revision 1: 11-Dec-2002: PCB footprint altered.; Revision 2: 19-Mar-2004: Silkscreen size reduced.; Package Information: Latest Revision: Mar-2001; Note: Footprint corresponds to dimensions for bulk cassette packaging. This case size has tightened tolerances.; Code - IPC: 2012[0805]; Dielectric: X5R
C25-C28 C30-C33 = C0805: Ceramic Chip Capacitor - Standard; Revision 1: 11-Dec-2002: PCB footprint altered.; Revision 2: 19-Mar-2004: Silkscreen size reduced.; Package Information: Latest Revision: Mar-2001; Note: Footprint corresponds to dimensions for bulk cassette packaging. This case size has tightened tolerances.; Code - IPC: 2012[0805]; Value: 0.1uF
C36-C38 C41 C43 C44 C48 = C0805: Ceramic Chip Capacitor - Standard; Revision 1: 11-Dec-2002: PCB footprint altered.; Revision 2: 19-Mar-2004: Silkscreen size reduced.; Package Information: Latest Revision: Mar-2001; Note: Footprint corresponds to dimensions for bulk cassette packaging. This case size has tightened tolerances.; Code - IPC: 2012[0805]; Dielectric: Y5V
C45 C49-C51 = Cap Pol2: Polarized Capacitor (Axial)
D1 = 10MQ060N: Schottky Rectifier; Package Information: Latest Revision: revH, May-2002
D2 = D Zener: Zener Diode
D3 D4 = BAS40DW-06
D5 D6 = Diode BAS70: Silicon AF Schottky Diode for High-Speed Switching; Package Information: Latest Revision: Sep-2001; Note: Pin 2 is not connected and not drawn.
F1 F2 = Fuseclip Mini vert: Value: #3544
JP1 JP2 = Socket: Manufacturer: Generic Components; Class I: Connector
JP3-JP8 = TERMINAL 10AWG: Value: 794037-1
JP9 = HEADER 8F SHROUDED
JP10 JP21 JP22 = HEADER 4 SHROUDED: Value: 644486-4
JP11 = Header 5X2: Header, 5-Pin, Dual row; Value: PPTC052LFBN
JP12 JP13 = Header 2: Header, 2-Pin
JP14-JP19 = HEADER 5X1: Value: MTA-50 vert 5pos
JP20 = HEADER 12F SHROUDED
JP23 JP24 = HEADER 8F LOW: Value: 87340-0822
L1-L3 = Inductor: Manufacturer: Generic Components; Class I: Passive
L4 = Inductor Iron: Magnetic-Core Inductor
Q1-Q8 Q14 Q16 = BC847C: NPN General-purpose Transistor; Package Information: Latest Revision: May-1999
Q9-Q12 = IRF7324: HEXFET Power MOSFET; Package Information: Latest Revision: Feb-2001; Code - JEDEC: MS-012-AA
Q13 Q15 Q17 Q19 Q21 Q22 = BC856BLT1: General Purpose Transistor PNP Silicon; Package Information: Latest Revision: 1997
Q18 Q20 Q23-Q26 Q31-Q33 Q35 = BC847CLT1: General Purpose Transistor NPN Silicon; Package Information: Latest Revision: 1997
Q27-Q30 Q36 Q37 = IRF2804: HEXFET Power MOSFET; Package Information: Latest Revision: Feb-1997; Note: Pin 2 is electrically connected to Tab (Drain).
Q34 = BSS84: P-Channel Enhancement Mode Vertical DMOS FET; Package Information: Latest Revision: 1996
R1-R18 R21 R22 R25 R26 R29 R30 R33-R73 R76 R77 R80 R81 R84 R85 R88-R103 R105 = ERJ6GE: Thick Film Chip Resistor, 1 Ohm to 10M Ohm Range, 5% Tolerance, 0805 Size, 0.125 W; Package Information: Latest Revision: Mar-2003; Note: If flow soldering, adjust pad width of PCB Footprint to 0.7 - 0.8 times the width of the resistor.; Code - IPC: 2012 [0805]
R19 R20 R23 R24 R27 R28 R31 R32 R74 R75 R78 R79 R82 R83 R86 R87 = Resistor 5W ceramic
U1 U2 = MSP430F133: Ultra Low Power 16 bit Mixed Signal uC
U3 U4 = BQ29312: Lithium Battery Protection Analog Front End
U5 U6 = LM7131ACM5: Tiny High-Speed Single-Supply Operational Amplifier; Package Information: Latest Revision: 2000
U8 = MC74VHC138D: 3-to-8 Line Decoder; Package Information: Latest Revision: Oct-1999; Code - JEDEC: MS-012-AC; Code - IPC: SO16
U10 = ICL7662CBD: CMOS Voltage Converter; Code - JEDEC: MS-012-AB; Code - IPC: SO14
U11 = MAX9075EUK-T: Low-Cost, Ultra-Small, 3µA Single-Supply Comparator
Y1-Y4 = XTAL: Crystal Oscillator; Manufacturer: Generic Components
